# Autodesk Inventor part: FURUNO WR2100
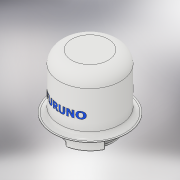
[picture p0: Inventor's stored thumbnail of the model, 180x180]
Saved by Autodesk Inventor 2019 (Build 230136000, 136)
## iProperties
Created: 2019-09
Part Number: FURUNO WR2100
Material: Genérico
Document SubType Name: Chapa
Designer: julio
Density: 1 g/cm^3
Sheet Metal Rule: Por defecto
Appearance: Blanco
Author: julio
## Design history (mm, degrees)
sketch "Boceto1"
  geometry: L1 (-119.033, 1664.431)-(2571.88, -490.997); L2 (2571.88, -490.997)-(1048.745, -2392.533); L3 (1048.745, -2392.533)-(-1642.168, -237.105); L4 (-1642.168, -237.105)-(-119.033, 1664.431); L5 (46.072, 334.247)-(-101.017, 452.066); L6 (-422.196, 202.063)-(-348.533, 143.059); L7 (-362.681, -93.422)-(-323.58, -124.742); A1 r 340 centre (-6.648, -1.641) between (46.072, 334.247) and (-323.58, -124.742); A2 r 467.499 centre (-3.084, -5.06) between (-101.017, 452.066) and (-422.196, 202.063); A3 r 403.887 centre (29.831, 1.757) between (-348.533, 143.059) and (-362.681, -93.422); 1 further point; 1 other entity
  constraints: 6 end point, 6 point on circle, 3 centre point, 2 parallel, 2 other
  dimensions: "d98" = 680 diameter of A1
extrude "Extrusión1" new body sketch "Boceto1" distance "d99" = 50; taper "d100" = 0 deg
sketch "Boceto2"
  geometry: L1 (-52.72, -335.888)-(94.369, -453.707) reference; L2 (415.548, -203.704)-(341.885, -144.7) reference; L3 (356.033, 91.781)-(316.932, 123.101) reference; A1 r 340 centre (0, 0) between (-52.72, -335.888) and (316.932, 123.101) reference; A2 r 467.499 centre (-3.564, 3.419) between (94.369, -453.707) and (415.548, -203.704) reference; A3 r 403.887 centre (-36.479, -3.398) between (341.885, -144.7) and (356.033, 91.781) reference; 1 further point
extrude "Extrusión2" join sketch "Boceto2" distance "d102" = 100; taper "d103" = 0 deg
sketch "Boceto3"
  geometry: C1 r 500 at (0, 0); 1 further point
  constraints: 1 centre point
  dimensions: "d104" = 1000 diameter of C1
extrude "Extrusión3" join sketch "Boceto3" distance "d105" = 75; taper "d106" = 0 deg
chamfer "Chaflán2" distance "d110" = 20; stored, may be unused: second distance "d111" = 2, angle "d112" = 45 deg
fillet "Empalme2" dims "d125" = 70
fillet "Empalme3" dims "d126" = 20
sketch "Boceto10"
  geometry: C1 r 542.5 at (-6.648, -1.641); 1 further point
  constraints: 1 centre point, 1 coincident
  dimensions: "d130" = 1085 diameter of C1
extrude "Extrusión5" join sketch "Boceto10" distance "d131" = 5; taper "d132" = 0 deg
sketch "Boceto11"
  geometry: C1 r 450 at (0, 0); 1 further point
  constraints: 1 centre point, 1 coincident
  dimensions: "d133" = 900 diameter of C1
extrude "Extrusión6" join sketch "Boceto11" distance "d134" = 800; taper "d135" = 0 deg
fillet "Empalme5" dims "d137" = 70
fillet "Empalme6" dims "d138" = 180
chamfer "Chaflán4" distance "d139" = 10; stored, may be unused: second distance "d140" = 2, angle "d141" = 45 deg
node "Plano de trabajo5"
sketch "Boceto20"
  geometry: L1 (-299.131, 325.284)-(295.764, 325.284); L2 (295.764, 325.284)-(295.764, 221.07); L3 (295.764, 221.07)-(-299.131, 221.07); L4 (-299.131, 221.07)-(-299.131, 325.284); 1 further point
  constraints: 2 other
feature "Repujado1" sketch "Boceto20" dims "d142" = 1, "d143" = 0
pattern_circular "Patrón circular1" dims angle "d145" = 180 deg
node "Sólido1"
node "Imagen1"
node "Contorno proyectado1"
other parameters: "Grosor" = 0.5, "FactorK" = 4.4, "Radio_pliegue" = 0.5 (= Grosor), "Anchura_desahogo_plegado" = 0.5 (= Grosor), "Profundidad_desahogo_plegado" = 0.25 (= 0.5 x Grosor), "Tamaño_destalonado" = 2 (= 4 x Grosor), "Separación_entre_unión" = 0.01, "Remanente_mínimo" = 1 (= 2 x Grosor), "Radiodetransición" = 0.5 (= Radio_pliegue), "Tamaño_de_radio_de_Jacobi" = 0.5 (= Grosor), "TamañoSeparación" = 0.5 (= Grosor)
